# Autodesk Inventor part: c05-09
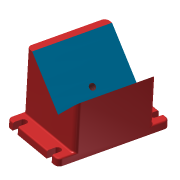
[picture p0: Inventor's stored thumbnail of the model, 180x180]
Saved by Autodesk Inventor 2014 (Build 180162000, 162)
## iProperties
Created: 2010-11
Part Number: c05-09
Material: Generic
Document SubType Name: Modeling
Designer: Thom Tremblay
Density: 1 g/cm^3
Appearance: Satin -Light Red
Author: Thom Tremblay
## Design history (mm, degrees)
sketch "Sketch1"
  geometry: L1 (-45, 0)-(45, 0); L2 (45, 0)-(45, 10); L3 (45, 10)-(-45, 10); L4 (-45, 10)-(-45, 0); L5 (-45, 10)-(-45, 90); L6 (-45, 90)-(-35, 90); L7 (-35, 90)-(14.497, 40.503); L8 (14.497, 40.503)-(45, 71.005); L9 (45, 71.005)-(45, 10); 2 further points
  constraints: 18 end point, 4 perpendicular, 3 collinear, 2 parallel, 2 point on line, 1 coincident, 1 horizontal, 1 midpoint
  dimensions: "d0" = 90 distance of L3.end L2.end; "d1" = 10 distance of L2.end L1.end; "d2" = 80 distance of L5.start L5.end; "d3" = 10 distance of L5.end L6.end; "d4" = 70 distance of L6.end L7.end; "d5" = 135 deg angle of L6 L7
extrude "Extrusion1" new body sketch "Sketch1" stored distance "d8" = 100; taper "d9" = 0 deg
extrude "Extrusion2" join sketch "Sketch1" stored distance "d10" = 140; taper "d11" = 0 deg
fillet "Fillet1" dims "d12" = 6
fillet "Fillet2" dims "d13" = 2
sketch "Sketch2"
  geometry: L1 (78, -2)-(0, -2) reference; L2 (-6, 4)-(-6, 132) reference; L3 (4.5, -2)-(13.5, -2); L4 (13.5, -2)-(13.5, 8); L5 (13.5, 8)-(4.5, 8); L6 (4.5, 8)-(4.5, -2); 2 further points
  constraints: 8 end point, 2 parallel, 1 horizontal, 1 horizontal alignment, 1 midpoint, 1 perpendicular, 1 point on line, 2 other
  dimensions: "d14" = 9 distance of L5.end L4.end; "d15" = 10 distance of L4.end L3.end; "d16" = 15 distance from line of point (9, 8) L2
extrude "Extrusion3" cut sketch "Sketch2" stored distance "d17" = 140; taper "d18" = 0 deg
mirror "Mirror1"
mirror "Mirror2"
hole "Hole1" diameter "d21" = 8.376; stored, may be unused: countersink angle "d25" = 90 deg, drill point angle "d27" = 118 deg; dims "d19" = 50, "d20" = 15, "d22" = 30, "d23" = 4, "d24" = 2, "d26" = 33.5
body "Solid1"
